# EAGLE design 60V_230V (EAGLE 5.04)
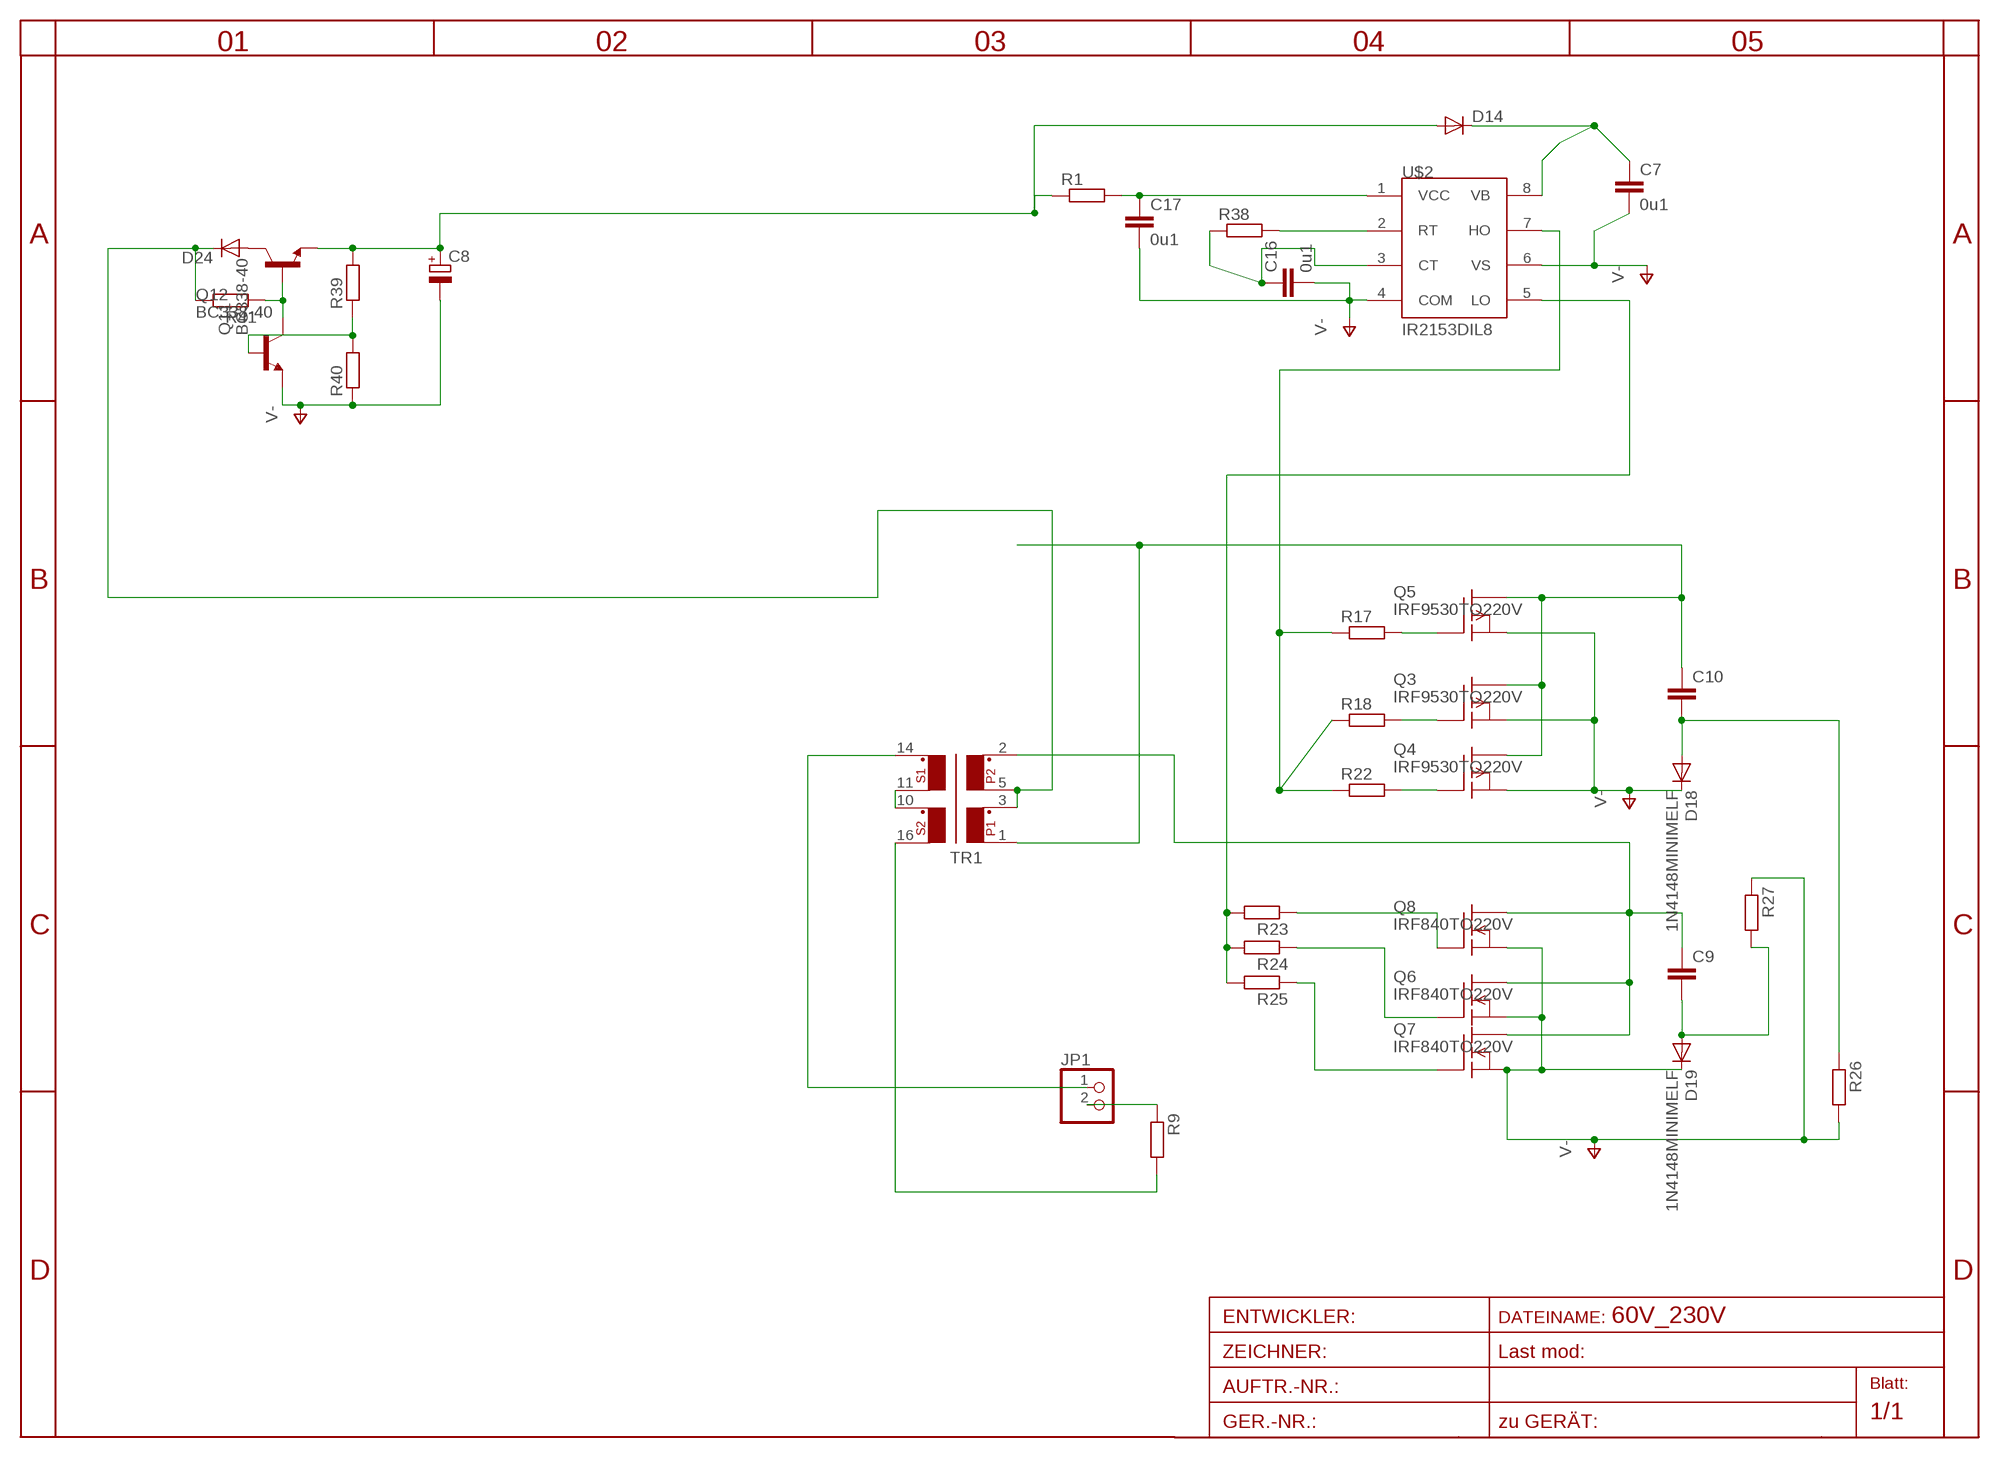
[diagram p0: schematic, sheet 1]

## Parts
C7  0u1  C-EU050-025X075  [C050-025X075]
C8  CPOL-EU5-13  [2,5-5-FLAT]
C9  C-EUC1812  [C1812]
C10  C-EUC1812K  [C1812K]
C16  0u1  C-EU025-050X050  [C025-050X050]
C17  0u1  C-EU050-030X075  [C050-030X075]
D14  DIODE-D-5  [D-5]
D18  1N4148MINIMELF  [MINIMELF]
D19  1N4148MINIMELF  [MINIMELF]
D24  DIODE-D-7.5  [D-7.5]
JP1  PINHD-1X2  [1X02]
Q3  IRF9530TO220V  [TO220V]
Q4  IRF9530TO220V  [TO220V]
Q5  IRF9530TO220V  [TO220V]
Q6  IRF840TO220V  [TO220V]
Q7  IRF840TO220V  [TO220V]
Q8  IRF840TO220V  [TO220V]
Q11  BC338-40  [TO92-EBC]
Q12  BC338-40  [TO92-EBC]
R1  R-EU_0204/2V  [0204V]
R9  R-EU_0207/10  [0207/10]
R17  R-EU_R1206  [R1206]
R18  R-EU_R1206  [R1206]
R22  R-EU_R1206  [R1206]
R23  R-EU_R1206  [R1206]
R24  R-EU_R1206  [R1206]
R25  R-EU_R1206  [R1206]
R26  R-EU_0207/25  [0207/25]
R27  R-EU_0207/30  [0207/30]
R38  R-EU_0204/2V  [0204V]
R39  R-EU_0207/10  [0207/10]
R40  R-EU_0204/2V  [0204V]
R41  R-EU_0207/10  [0207/10]
TR1  FL52EP16CONR  [EP16]
U$2  IR2153DIL8  [DIL08]

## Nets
CT: C16.1 R38.1 U$2.3(CT)
GATE: R17.1 R18.1 R22.1 U$2.7(HO)
N$1: JP1.2 R9.1
N$2: C9.1 Q6.2(D) Q7.2(D) Q8.2(D) TR1.2
N$3: TR1.10 TR1.11
N$4: Q3.1(G) R18.2
N$5: C8.+ D14.A Q11.E R1.1 R39.2
N$6: C10.1 Q3.2(D) Q4.2(D) Q5.2(D) TR1.1
N$7: JP1.1 TR1.14
N$8: R9.2 TR1.16
N$9: R23.2 R24.2 R25.2 U$2.5(LO)
N$11: Q5.1(G) R17.2
N$23: Q4.1(G) R22.2
N$24: C10.2 D18.A R26.1
N$25: Q7.1(G) R25.1
N$26: Q6.1(G) R24.1
N$27: Q8.1(G) R23.1
N$28: C9.2 D19.A R27.2
N$36: D24.A Q11.C
N$38: Q11.B Q12.C R41.1
N$40: R38.2 U$2.2(RT)
N$41: Q12.B R39.1 R40.2
V-: C7.2 C8.- C16.2 C17.2 D18.C D19.C Q3.3(S) Q4.3(S) Q5.3(S) Q6.3(S) Q7.3(S) Q8.3(S) Q12.E R26.2 R27.1 R40.1 U$2.4(COM) U$2.6(VS)
VB: C7.1 D14.C U$2.8(VB)
VCC: C17.1 R1.2 U$2.1(VCC)
VIN: D24.C R41.2 TR1.3 TR1.5

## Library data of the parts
C7 C9 C10 C16 C17 = rcl-2:C-EU: CAPACITOR, European symbol
C8 = rcl-2:CPOL-EU: POLARIZED CAPACITOR, European symbol
D14 D24 = diode-1:DIODE-: DIODE
D18 D19 = diode-1:1N4148: DIODE
JP1 = pinhead:PINHD-1X2: PIN HEADER
Q3-Q5 = transistor-fet:IRF9530: P-Channel Enhancement MOSFET (HEXFET); -100V; -12A; 0,3Ohm
Q6-Q8 = transistor-fet:IRF840: N-Channel Enhancement MOSFET (HEXFET); 500V; 8A; 0,85Ohm
Q11 Q12 = transistor-npn:BC338*: NPN Transistor
R1 R9 R17 R18 R22-R27 R38-R41 = rcl-2:R-EU_: RESISTOR, European symbol
TR1 = trafo:FL52: TRANSFORMER 2 primary winding, 2 secondary windings, mounting holes BLOCK
U$2 = irf-2:IR2153

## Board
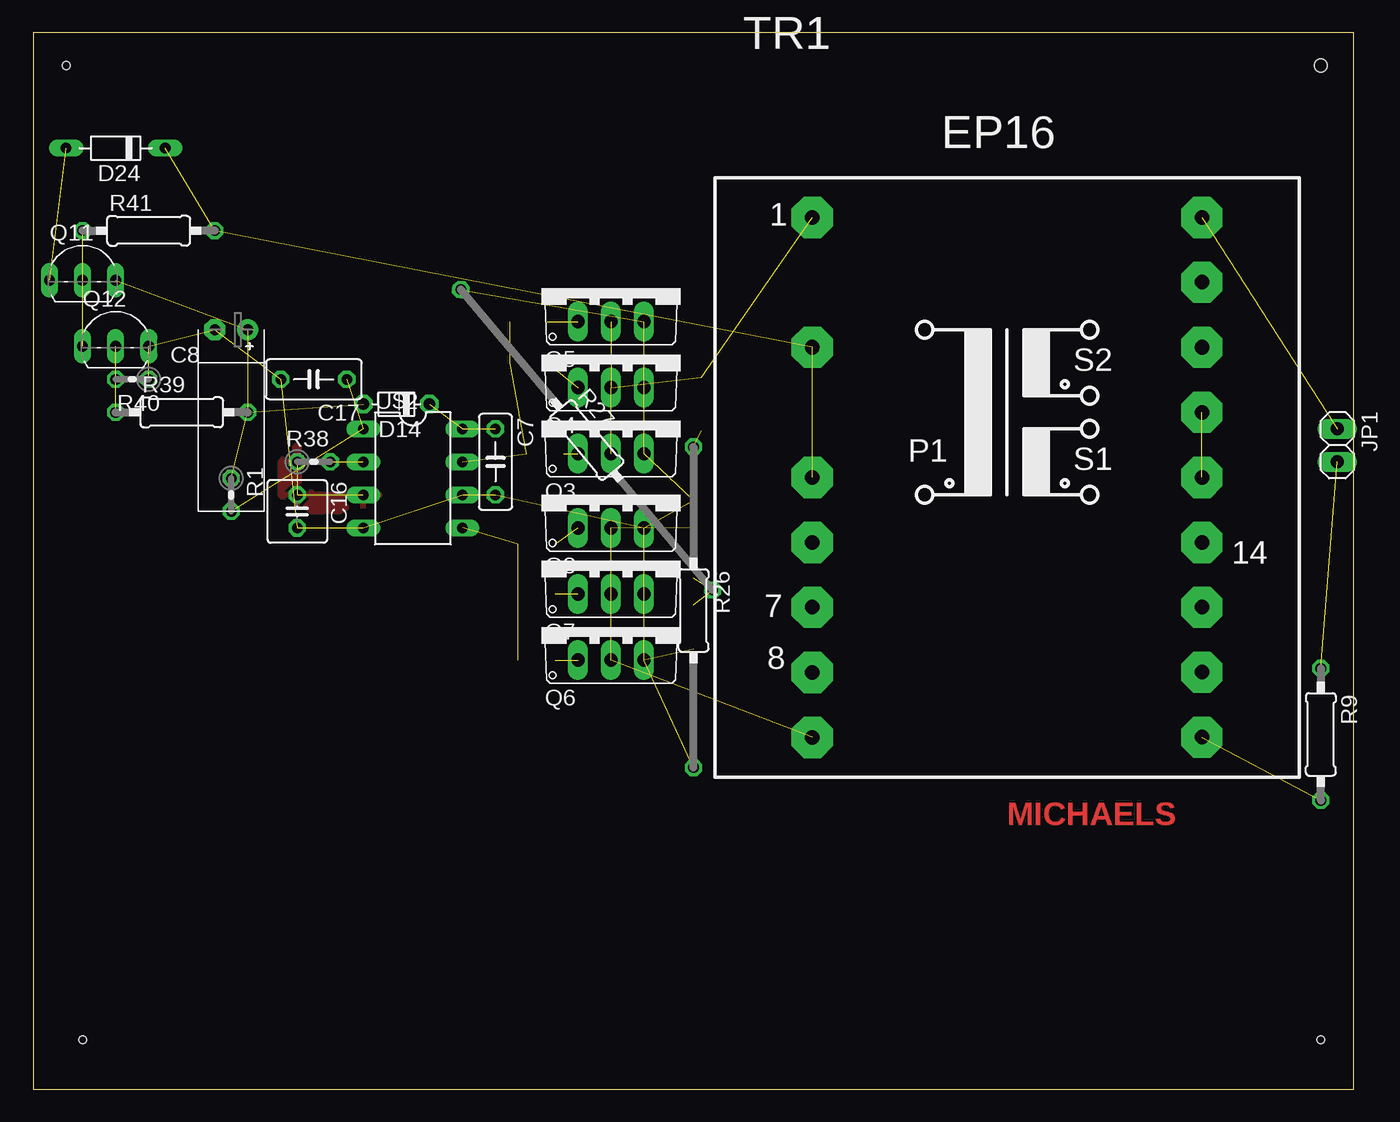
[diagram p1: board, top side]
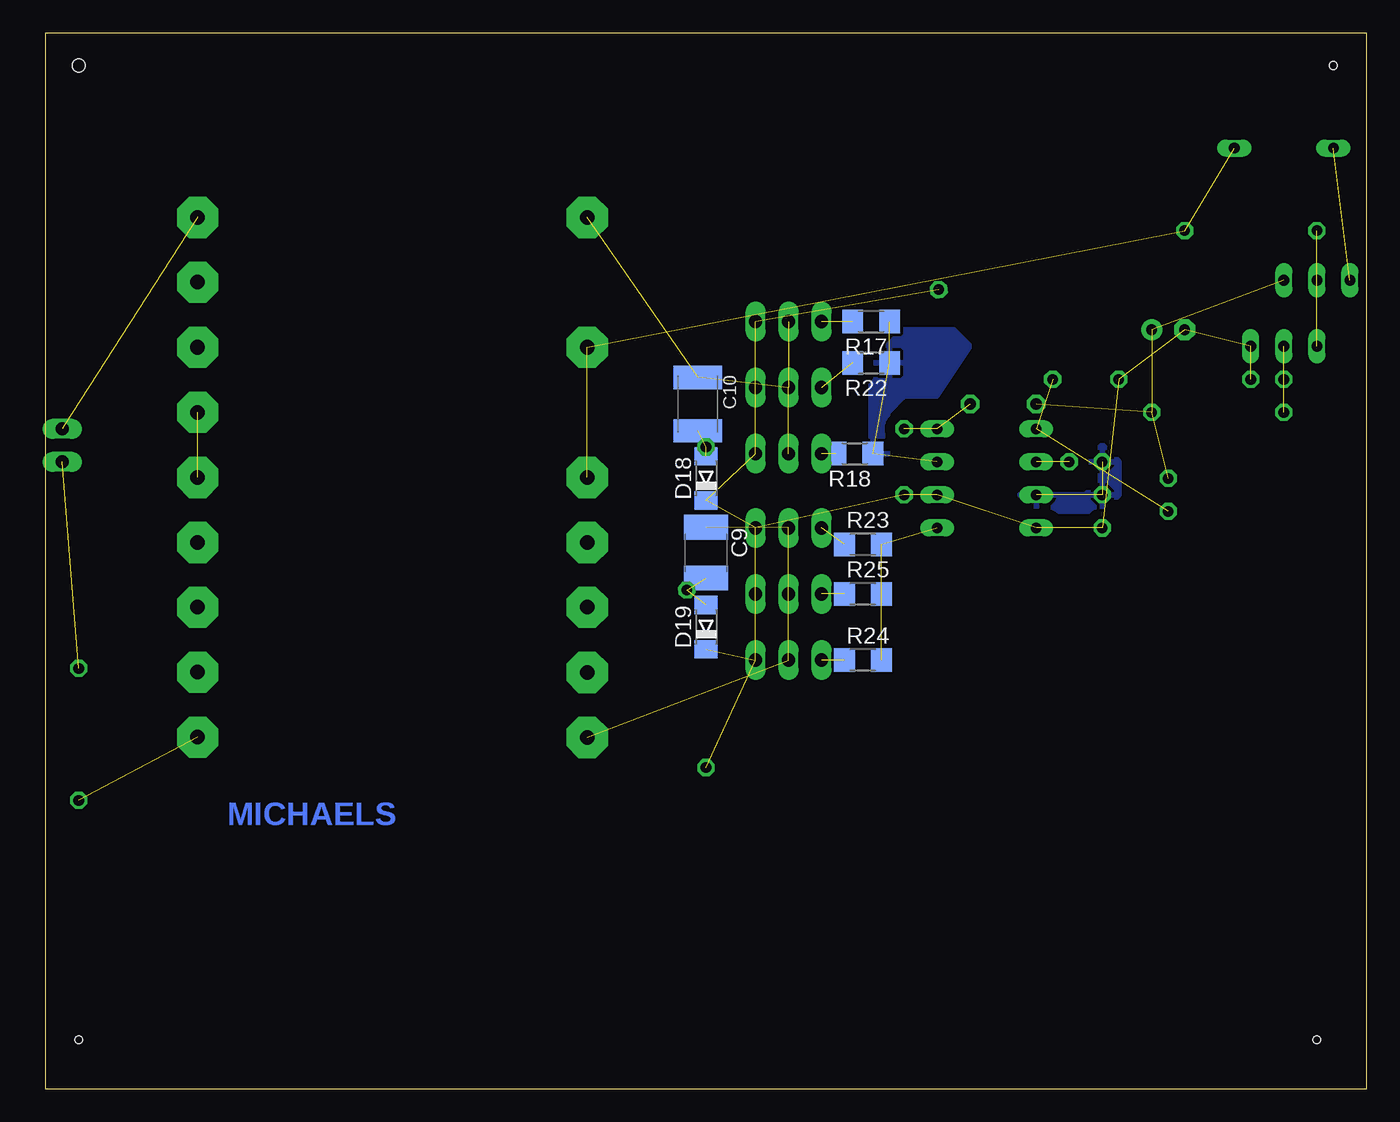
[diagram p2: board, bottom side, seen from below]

Size 101.6 x 81.28 mm. Coordinates in mm from the lower left corner, seen from the top.
Outline: 0,0 101.6,0 101.6,81.28 0,81.28 0,0
Copper layers (1*16): Top 0.035mm / dielectric 1.5mm / Bottom 0.035mm
Design rules "default": minimum track width 10mil, minimum drill 24mil, track to track 8mil, track to pad 8mil, pad to pad 8mil, via to via 8mil, smd to smd 8mil, copper to edge 40mil, drill to drill 8mil, minimum pad ring 10mil, minimum via ring 8mil, stop-mask expansion 4mil, vias tented up to drill 0mil, thermal gap 10mil
Holes 0.6 mm at 2.54,78.74 3.81,3.81 99.06,3.81
Holes 1 mm at 99.06,78.74

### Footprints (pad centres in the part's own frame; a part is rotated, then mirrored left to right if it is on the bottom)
C050-025X075 = drill 0.813 octagon: 1 -2.54,0; 2 2.54,0
2,5-5-FLAT = drill 0.813 pad 1.6 round: + -1.27,0 | drill 0.813 pad 1.6 octagon: - 1.27,0
C1812 = smd 1.9 x 3.4: 1 -1.95,0; 2 1.95,0
C1812K = smd 1.8 x 3.7: 1 -2.05,0; 2 2.05,0
C025-050X050 = drill 0.813 octagon: 1 -1.27,0; 2 1.27,0
C050-030X075 = drill 0.813 octagon: 1 -2.54,0; 2 2.54,0
D-5 = drill 0.9 octagon: A 2.54,0; C -2.54,0
MINIMELF = smd 1.4 x 1.8: A 1.7,0; C -1.7,0
D-7.5 = drill 0.813 long: A 3.81,0; C -3.81,0
1X02 = drill 1.016 long: 1 -1.27,0; 2 1.27,0
TO220V = drill 1.016 long: 1 -2.54,-2.54; 2 0,-2.54; 3 2.54,-2.54
TO92-EBC = drill 0.813 long: B 0,-1.27; C -2.54,-1.27; E 2.54,-1.27
0204V = drill 0.813 octagon: 1 -1.27,0; 2 1.27,0
0207/10 = drill 0.813 octagon: 1 -5.08,0; 2 5.08,0
R1206 = smd 1.6 x 1.803: 1 -1.422,0; 2 1.422,0
0207/25 = drill 0.813 octagon: 1 -12.58,0; 2 12.08,0
0207/30 = drill 0.813 octagon: 1 -15.08,0; 2 15.08,0
EP16 = drill 1.118 pad 3.175 octagon: 1 -14.986,14.986; 2 -14.986,-25; 3 -14.986,5.004; 4 -14.986,-20; 5 -14.986,-5.004; 6 -14.986,-10.008; 7 -14.986,-14.986; 8 14.986,-14.986; 9 14.986,-10.008; 10 14.986,-5.004; 11 14.986,0; 12 14.986,5.004; 13 14.986,10.008; 14 14.986,14.986; 15 14.986,-19.986; 16 14.986,-24.986
DIL08 = drill 0.813 long: 1 -3.81,-3.81; 2 -1.27,-3.81; 3 1.27,-3.81; 4 3.81,-3.81; 5 3.81,3.81; 6 1.27,3.81; 7 -1.27,3.81; 8 -3.81,3.81

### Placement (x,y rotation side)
C7  35.56,48.26 270 top
C8  15.24,58.42 180 top
C9  50.8,41.27 270 bottom
C10  51.44,52.7 270 bottom
C16  20.32,44.45 270 top
C17  21.59,54.61 180 top
D14  27.94,52.7 180 top
D18  50.8,46.99 90 bottom
D19  50.8,35.56 90 bottom
D24  6.35,72.39 180 top
JP1  100.33,49.53 270 top
Q3  44.45,51.44 0 top
Q4  44.45,56.52 0 top
Q5  44.45,61.59 0 top
Q6  44.45,35.56 0 top
Q7  44.45,40.64 0 top
Q8  44.45,45.72 0 top
Q11  3.81,63.5 0 top
Q12  6.35,58.42 0 top
R1  15.24,45.72 270 top
R9  99.06,27.3 270 top
R17  38.1,59.05 180 bottom
R18  39.37,48.9 180 bottom
R22  38.1,55.88 180 bottom
R23  38.73,41.91 0 bottom
R24  38.73,33.02 0 bottom
R25  38.73,38.1 0 bottom
R26  50.8,36.83 270 top
R27  42.58,49.95 310 top
R38  21.59,48.26 0 top
R39  11.43,52.07 0 top
R40  7.62,54.61 180 top
R41  8.89,66.04 0 top
TR1  74.93,52.07 0 top
U$2  29.21,46.99 270 top

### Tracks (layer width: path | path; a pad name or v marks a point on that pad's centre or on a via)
CT  (2 unrouted)
  pour Bottom (isolate 0.813, rank 3): 26.67,45.72 21.59,45.72 20.32,46.99 21.59,48.26 20.32,49.53 19.05,48.26 19.05,45.72 20.32,44.45 25.4,44.45
  pour Top (isolate 0.813, rank 3): 26.67,45.72 21.59,45.72 20.32,46.99 21.59,48.26 20.32,49.53 19.05,48.26 19.05,45.72 20.32,44.45 25.4,44.45
GATE  (3 unrouted)
  pour Bottom (isolate 0.813, rank 2): 30.48,57.15 31.75,58.42 35.56,58.42 38.1,55.88 38.1,48.26 36.83,48.26 36.83,52.07 35.56,53.34 33.02,53.34
N$1  (1 unrouted)
N$2  (4 unrouted)
N$3  (1 unrouted)
N$4  (1 unrouted)
N$5  (4 unrouted)
N$6  (4 unrouted)
N$7  (1 unrouted)
N$8  (1 unrouted)
N$9  (3 unrouted)
N$11  (1 unrouted)
N$23  (1 unrouted)
N$24  (2 unrouted)
N$25  (1 unrouted)
N$26  (1 unrouted)
N$27  (1 unrouted)
N$28  (2 unrouted)
N$36  (1 unrouted)
N$38  (2 unrouted)
N$40  (1 unrouted)
N$41  (2 unrouted)
V-  (17 unrouted)
VB  (2 unrouted)
VCC  (2 unrouted)
VIN  (3 unrouted)

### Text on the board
Top: MICHAELS
Bottom: MICHAELS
